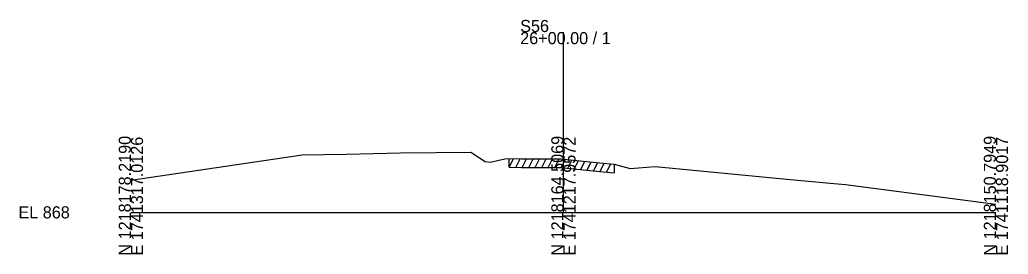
# Model space of a CAD drawing. Extents: x -26 to 1203, y -10 to 19541.
# Drawn here: x -25.7 to 202.8, y 990.3 to 1044.5 of the extents above; entities that cross this region are included whole.
import ezdxf

# ---------------------------------------------------------------- set-up
doc = ezdxf.new("R2010")
doc.units = 0
for name, color, linetype in [('RD_GPK_XS_Cell', 7, 'Continuous'), ('RD_XS_ExGround', 7, 'Continuous'), ('RD_XS_ExPaveRet', 7, 'Continuous'), ('RD_XS_TX_Elev_EX', 7, 'Continuous')]:
    doc.layers.add(name, color=color, linetype=linetype)

msp = doc.modelspace()

# ---------------------------------------------------------------- linework, layer by layer
at = {"layer": 'RD_GPK_XS_Cell'}
for p, q in [((100, 1000), (100, 1041.7)), ((0, 1000), (100, 1000)), ((100, 1000), (200, 1000))]:
    msp.add_line(p, q, dxfattribs=at)
at = {"layer": 'RD_XS_ExGround'}
msp.add_lwpolyline([(0, 1007.42), (39.59, 1013.3), (49.88, 1013.42), (62.35, 1013.73), (78.63, 1013.9), (81.88, 1011.75), (83.09, 1011.6), (86.49, 1012.4), (87.49, 1012.42), (90.31, 1012.37), (99.5, 1012.35), (100, 1012.3), (108.41, 1011.45), (111.71, 1011.16), (115.42, 1010.15), (121.19, 1010.64), (151.67, 1007.7), (161.7, 1006.77), (165.24, 1006.43), (200, 1001.92)], dxfattribs=at)
at = {"layer": 'RD_XS_ExPaveRet'}
for p, q in [((87.49, 1010.42), (87.49, 1012.42)), ((87.49, 1010.42), (88.48, 1012.4)), ((87.49, 1010.42), (90.31, 1010.37)), ((88.99, 1010.39), (89.98, 1012.37)), ((90.31, 1010.37), (99.5, 1010.35)), ((90.49, 1010.37), (91.49, 1012.36)), ((91.99, 1010.36), (92.99, 1012.36)), ((93.49, 1010.36), (94.49, 1012.36)), ((94.99, 1010.36), (95.99, 1012.35)), ((96.49, 1010.35), (97.49, 1012.35)), ((97.99, 1010.35), (98.99, 1012.35)), ((99.49, 1010.35), (100.45, 1012.25)), ((99.5, 1010.35), (100, 1010.3)), ((100, 1010.3), (108.41, 1009.45)), ((100.99, 1010.2), (101.95, 1012.1)), ((102.49, 1010.05), (103.45, 1011.95)), ((103.99, 1009.9), (104.95, 1011.8)), ((105.49, 1009.75), (106.45, 1011.65)), ((106.99, 1009.6), (107.95, 1011.5)), ((108.49, 1009.45), (109.45, 1011.36)), ((109.99, 1009.31), (110.95, 1011.23)), ((111.71, 1011.16), (111.71, 1009.16)), ((108.41, 1009.45), (111.71, 1009.16))]:
    msp.add_line(p, q, dxfattribs=at)

# ---------------------------------------------------------------- texts
at = {"layer": 'RD_GPK_XS_Cell'}
for s, p in [('S56', (90, 1041.7)), ('26+00.00 / 1', (90, 1038.9)), ('EL 868', (-26, 998.6))]:
    msp.add_text(s, height=2.8, dxfattribs=at).set_placement(p)
for s, p in [('N 1218178.2190', (0, 990)), ('E 1741317.0126', (2.8, 990)), ('N 1218164.5069', (100, 990)), ('E 1741217.9572', (102.8, 990)), ('N 1218150.7949', (200, 990)), ('E 1741118.9017', (202.8, 990))]:
    msp.add_text(s, height=2.8, rotation=90, dxfattribs=at).set_placement(p)
at = {"layer": 'RD_XS_TX_Elev_EX'}
msp.add_text('874.15', height=0.1, rotation=90, dxfattribs=at).set_placement((100.1, 1012.3))

doc.saveas('drawing.dxf')
